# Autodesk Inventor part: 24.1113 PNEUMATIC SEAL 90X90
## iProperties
Created: 2007-06
Part Number: 24.1113 PNEUMATIC SEAL 90X90
Document SubType Name: Modeling
Designer: Andy Moles
Density: 1 g/cm^3
Author: Andy Moles
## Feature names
1. Extrusion1
2. Fillet1
